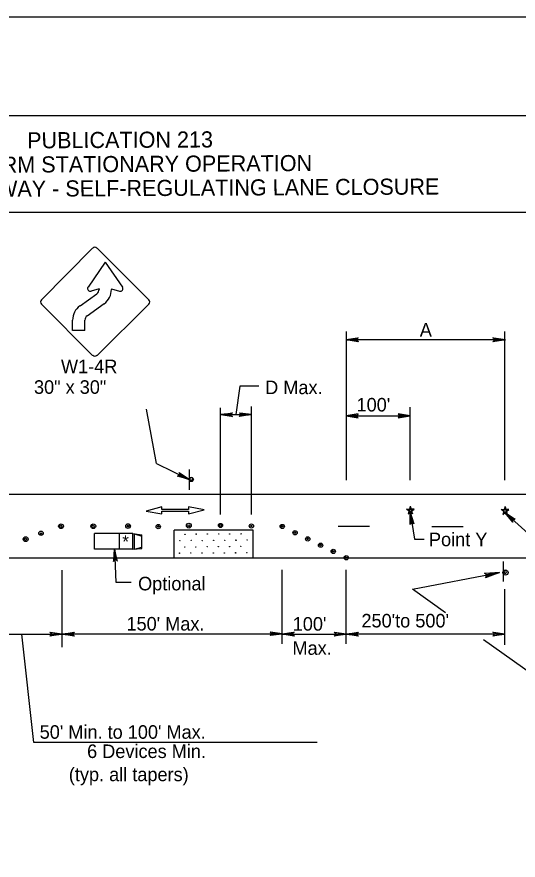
# Model space of a CAD drawing. Extents: x -14145 to -13521, y 30244 to 30661.
# Drawn here: x -13810.13 to -13802.36, y 30356.22 to 30369.31 of the extents above; entities that cross this region are included whole.
import ezdxf

# ---------------------------------------------------------------- set-up
doc = ezdxf.new("R2010")
doc.units = 0
for name, color, linetype in [('1', 7, 'Continuous'), ('10', 7, 'Continuous'), ('2', 7, 'Continuous'), ('3', 7, 'Continuous'), ('4', 7, 'Continuous'), ('61', 7, 'Continuous')]:
    doc.layers.add(name, color=color, linetype=linetype)

msp = doc.modelspace()

# ---------------------------------------------------------------- linework, layer by layer
at = {"layer": '1'}
for p, q in [((-13808.954, 30365.72), (-13809.748, 30364.917)), ((-13808.084, 30364.917), (-13808.886, 30365.72)), ((-13808.76, 30365.501), (-13809.026, 30365.114)), ((-13808.76, 30365.501), (-13808.49, 30365.114)), ((-13808.854, 30365.09), (-13808.978, 30365.051)), ((-13808.854, 30365.09), (-13808.854, 30365.078)), ((-13808.664, 30365.09), (-13808.538, 30365.051)), ((-13808.664, 30365.09), (-13808.664, 30365.079)), ((-13809.15, 30364.822), (-13808.888, 30365.012)), ((-13809.748, 30364.851), (-13808.954, 30364.056)), ((-13809.04, 30364.668), (-13808.776, 30364.858)), ((-13808.886, 30364.056), (-13808.084, 30364.851)), ((-13809.264, 30364.44), (-13809.264, 30364.601)), ((-13809.074, 30364.44), (-13809.074, 30364.603)), ((-13809.074, 30364.44), (-13809.264, 30364.44)), ((-13805.025, 30364.425), (-13805.025, 30362.12)), ((-13802.565, 30362.12), (-13802.565, 30364.426)), ((-13802.559, 30364.297), (-13805.025, 30364.297)), ((-13807.963, 30362.379), (-13808.121, 30363.219)), ((-13806.975, 30361.588), (-13806.975, 30363.244)), ((-13806.495, 30361.588), (-13806.495, 30363.262)), ((-13804.035, 30362.12), (-13804.035, 30363.25)), ((-13806.975, 30363.136), (-13806.495, 30363.136)), ((-13805.025, 30363.116), (-13804.035, 30363.116)), ((-13807.963, 30362.379), (-13807.457, 30362.128)), ((-13807.457, 30362.287), (-13807.457, 30361.969)), ((-13821.541, 30361.9), (-13795.261, 30361.9)), ((-13807.884, 30361.707), (-13808.125, 30361.641)), ((-13808.125, 30361.641), (-13807.881, 30361.595)), ((-13807.884, 30361.662), (-13807.884, 30361.707)), ((-13807.47, 30361.662), (-13807.884, 30361.662)), ((-13807.881, 30361.64), (-13807.467, 30361.64)), ((-13807.881, 30361.595), (-13807.881, 30361.64)), ((-13807.226, 30361.661), (-13807.47, 30361.707)), ((-13807.47, 30361.707), (-13807.47, 30361.662)), ((-13807.467, 30361.595), (-13807.226, 30361.661)), ((-13807.467, 30361.64), (-13807.467, 30361.595)), ((-13804.092, 30361.669), (-13804.046, 30361.669)), ((-13804.054, 30361.639), (-13804.092, 30361.669)), ((-13804.051, 30361.64), (-13804.085, 30361.666)), ((-13804.085, 30361.666), (-13804.044, 30361.666)), ((-13804.048, 30361.641), (-13804.078, 30361.664)), ((-13804.078, 30361.664), (-13804.042, 30361.664)), ((-13804.046, 30361.642), (-13804.071, 30361.661)), ((-13804.071, 30361.661), (-13804.04, 30361.661)), ((-13804.051, 30361.64), (-13804.062, 30361.602)), ((-13804.048, 30361.641), (-13804.058, 30361.608)), ((-13804.046, 30361.642), (-13804.053, 30361.615)), ((-13804.032, 30361.715), (-13804.046, 30361.669)), ((-13804.032, 30361.706), (-13804.044, 30361.666)), ((-13804.032, 30361.697), (-13804.042, 30361.664)), ((-13804.032, 30361.687), (-13804.04, 30361.661)), ((-13804.032, 30361.715), (-13804.019, 30361.669)), ((-13804.032, 30361.706), (-13804.021, 30361.666)), ((-13804.032, 30361.697), (-13804.023, 30361.664)), ((-13804.032, 30361.687), (-13804.025, 30361.661)), ((-13803.994, 30361.661), (-13804.025, 30361.661)), ((-13803.987, 30361.664), (-13804.023, 30361.664)), ((-13803.98, 30361.666), (-13804.021, 30361.666)), ((-13803.972, 30361.669), (-13804.019, 30361.669)), ((-13804.019, 30361.642), (-13803.994, 30361.661)), ((-13804.019, 30361.642), (-13804.012, 30361.615)), ((-13804.016, 30361.641), (-13803.987, 30361.664)), ((-13804.016, 30361.641), (-13804.007, 30361.608)), ((-13804.014, 30361.64), (-13803.98, 30361.666)), ((-13804.014, 30361.64), (-13804.003, 30361.602)), ((-13804.011, 30361.639), (-13803.972, 30361.669)), ((-13802.623, 30361.663), (-13802.577, 30361.663)), ((-13802.585, 30361.633), (-13802.623, 30361.663)), ((-13802.582, 30361.634), (-13802.616, 30361.66)), ((-13802.616, 30361.66), (-13802.575, 30361.66)), ((-13802.579, 30361.635), (-13802.609, 30361.658)), ((-13802.609, 30361.658), (-13802.573, 30361.658)), ((-13802.577, 30361.636), (-13802.602, 30361.655)), ((-13802.602, 30361.655), (-13802.571, 30361.655)), ((-13802.563, 30361.709), (-13802.577, 30361.663)), ((-13802.563, 30361.7), (-13802.575, 30361.66)), ((-13802.563, 30361.691), (-13802.573, 30361.658)), ((-13802.563, 30361.681), (-13802.571, 30361.655)), ((-13802.563, 30361.709), (-13802.55, 30361.663)), ((-13802.563, 30361.7), (-13802.552, 30361.66)), ((-13802.563, 30361.691), (-13802.554, 30361.658)), ((-13802.563, 30361.681), (-13802.556, 30361.655)), ((-13802.525, 30361.655), (-13802.556, 30361.655)), ((-13802.518, 30361.658), (-13802.554, 30361.658)), ((-13802.511, 30361.66), (-13802.552, 30361.66)), ((-13802.503, 30361.663), (-13802.55, 30361.663)), ((-13802.55, 30361.636), (-13802.525, 30361.655)), ((-13802.547, 30361.635), (-13802.518, 30361.658)), ((-13802.545, 30361.634), (-13802.511, 30361.66)), ((-13802.542, 30361.633), (-13802.503, 30361.663)), ((-13804.054, 30361.639), (-13804.067, 30361.595)), ((-13804.067, 30361.595), (-13804.032, 30361.622)), ((-13804.062, 30361.602), (-13804.032, 30361.625)), ((-13804.058, 30361.608), (-13804.032, 30361.628)), ((-13804.053, 30361.615), (-13804.032, 30361.631)), ((-13804.012, 30361.615), (-13804.032, 30361.631)), ((-13804.007, 30361.608), (-13804.032, 30361.628)), ((-13804.003, 30361.602), (-13804.032, 30361.625)), ((-13803.998, 30361.595), (-13804.032, 30361.622)), ((-13804.011, 30361.639), (-13803.998, 30361.595)), ((-13802.585, 30361.633), (-13802.598, 30361.589)), ((-13802.598, 30361.589), (-13802.563, 30361.616)), ((-13802.582, 30361.634), (-13802.593, 30361.596)), ((-13802.593, 30361.596), (-13802.563, 30361.619)), ((-13802.579, 30361.635), (-13802.589, 30361.602)), ((-13802.589, 30361.602), (-13802.563, 30361.622)), ((-13802.577, 30361.636), (-13802.584, 30361.609)), ((-13802.584, 30361.609), (-13802.563, 30361.625)), ((-13802.543, 30361.609), (-13802.563, 30361.625)), ((-13802.538, 30361.602), (-13802.563, 30361.622)), ((-13802.534, 30361.596), (-13802.563, 30361.619)), ((-13802.529, 30361.589), (-13802.563, 30361.616)), ((-13802.55, 30361.636), (-13802.543, 30361.609)), ((-13802.547, 30361.635), (-13802.538, 30361.602)), ((-13802.545, 30361.634), (-13802.534, 30361.596)), ((-13802.542, 30361.633), (-13802.529, 30361.589)), ((-13804.665, 30361.402), (-13805.151, 30361.402)), ((-13803.213, 30361.396), (-13803.699, 30361.396)), ((-13808.923, 30361.048), (-13808.923, 30361.294)), ((-13808.329, 30361.294), (-13808.923, 30361.294)), ((-13808.539, 30361.048), (-13808.539, 30361.294)), ((-13808.329, 30361.048), (-13808.329, 30361.294)), ((-13808.329, 30361.294), (-13808.191, 30361.27)), ((-13808.305, 30361.288), (-13808.191, 30361.252)), ((-13808.305, 30361.048), (-13808.305, 30361.288)), ((-13808.191, 30361.06), (-13808.191, 30361.27)), ((-13806.469, 30361.342), (-13807.693, 30361.342)), ((-13807.693, 30360.916), (-13807.693, 30361.342)), ((-13806.469, 30360.916), (-13806.469, 30361.342)), ((-13808.329, 30361.048), (-13808.923, 30361.048)), ((-13808.329, 30361.048), (-13808.191, 30361.06)), ((-13808.305, 30361.048), (-13808.191, 30361.078)), ((-13821.541, 30360.916), (-13795.261, 30360.916)), ((-13802.595, 30360.858), (-13802.595, 30360.546)), ((-13806.017, 30359.582), (-13806.017, 30360.728)), ((-13805.025, 30359.582), (-13805.025, 30360.728)), ((-13809.425, 30359.528), (-13809.425, 30360.722)), ((-13802.565, 30359.563), (-13802.565, 30360.427)), ((-13810.679, 30359.732), (-13809.431, 30359.732)), ((-13806.017, 30359.732), (-13809.425, 30359.732)), ((-13806.017, 30359.732), (-13805.025, 30359.732)), ((-13802.565, 30359.732), (-13805.025, 30359.732))]:
    msp.add_line(p, q, dxfattribs=at)
for points in [[(-13804.845, 30364.279), (-13804.851, 30364.291), (-13805.025, 30364.297), (-13804.845, 30364.279), (-13804.839, 30364.267), (-13805.025, 30364.297), (-13804.857, 30364.309), (-13804.851, 30364.321), (-13805.025, 30364.297), (-13804.839, 30364.327), (-13804.851, 30364.321)], [(-13802.739, 30364.321), (-13802.733, 30364.309), (-13802.559, 30364.297), (-13802.739, 30364.321), (-13802.751, 30364.327), (-13802.559, 30364.297), (-13802.733, 30364.291), (-13802.739, 30364.279), (-13802.559, 30364.297), (-13802.751, 30364.267), (-13802.739, 30364.279)], [(-13806.377, 30363.58), (-13806.671, 30363.58), (-13806.735, 30363.136)], [(-13806.801, 30363.112), (-13806.807, 30363.124), (-13806.975, 30363.136), (-13806.801, 30363.112), (-13806.789, 30363.106), (-13806.975, 30363.136), (-13806.807, 30363.142), (-13806.801, 30363.154), (-13806.975, 30363.136), (-13806.789, 30363.166), (-13806.801, 30363.154)], [(-13806.675, 30363.16), (-13806.669, 30363.148), (-13806.495, 30363.136), (-13806.675, 30363.16), (-13806.681, 30363.166), (-13806.495, 30363.136), (-13806.669, 30363.13), (-13806.675, 30363.118), (-13806.495, 30363.136), (-13806.681, 30363.106), (-13806.675, 30363.118)], [(-13804.845, 30363.134), (-13804.857, 30363.122), (-13805.025, 30363.116), (-13804.845, 30363.134), (-13804.839, 30363.146), (-13805.025, 30363.116), (-13804.857, 30363.104), (-13804.851, 30363.092), (-13805.025, 30363.116), (-13804.839, 30363.086), (-13804.851, 30363.092)], [(-13804.215, 30363.092), (-13804.203, 30363.11), (-13804.035, 30363.116), (-13804.215, 30363.092), (-13804.221, 30363.086), (-13804.035, 30363.116), (-13804.203, 30363.122), (-13804.209, 30363.14), (-13804.035, 30363.116), (-13804.221, 30363.146), (-13804.209, 30363.14)], [(-13807.609, 30362.227), (-13807.609, 30362.21), (-13807.457, 30362.128), (-13807.609, 30362.227), (-13807.611, 30362.236), (-13807.457, 30362.128), (-13807.615, 30362.193), (-13807.627, 30362.188), (-13807.457, 30362.128), (-13807.641, 30362.182), (-13807.627, 30362.188)], [(-13804.029, 30361.44), (-13804.013, 30361.454), (-13804.033, 30361.621), (-13804.029, 30361.44), (-13804.033, 30361.432), (-13804.033, 30361.621), (-13804.001, 30361.456), (-13803.983, 30361.453), (-13804.033, 30361.621), (-13803.975, 30361.442), (-13803.983, 30361.453)], [(-13802.446, 30361.477), (-13802.442, 30361.498), (-13802.563, 30361.615), (-13802.446, 30361.477), (-13802.445, 30361.468), (-13802.563, 30361.615), (-13802.434, 30361.507), (-13802.418, 30361.516), (-13802.563, 30361.615), (-13802.406, 30361.512), (-13802.418, 30361.516)], [(-13808.583, 30360.876), (-13808.595, 30360.882), (-13808.613, 30361.048), (-13808.583, 30360.876), (-13808.571, 30360.865), (-13808.613, 30361.048), (-13808.613, 30360.88), (-13808.625, 30360.874), (-13808.613, 30361.048), (-13808.631, 30360.86), (-13808.625, 30360.874)], [(-13808.356, 30360.53), (-13808.592, 30360.53), (-13808.612, 30361.048)], [(-13805.477, 30358.052), (-13809.867, 30358.052), (-13810.054, 30359.732)], [(-13809.611, 30359.756), (-13809.599, 30359.738), (-13809.431, 30359.732), (-13809.611, 30359.756), (-13809.617, 30359.762), (-13809.431, 30359.732), (-13809.599, 30359.726), (-13809.605, 30359.708), (-13809.431, 30359.732), (-13809.617, 30359.702), (-13809.605, 30359.708)], [(-13809.245, 30359.708), (-13809.251, 30359.72), (-13809.425, 30359.732), (-13809.245, 30359.708), (-13809.239, 30359.702), (-13809.425, 30359.732), (-13809.251, 30359.738), (-13809.245, 30359.75), (-13809.425, 30359.732), (-13809.239, 30359.762), (-13809.245, 30359.75)], [(-13806.197, 30359.762), (-13806.191, 30359.744), (-13806.017, 30359.738), (-13806.197, 30359.762), (-13806.203, 30359.768), (-13806.017, 30359.738), (-13806.191, 30359.732), (-13806.197, 30359.714), (-13806.017, 30359.738), (-13806.203, 30359.708), (-13806.197, 30359.714)], [(-13805.837, 30359.714), (-13805.849, 30359.726), (-13806.017, 30359.732), (-13805.837, 30359.714), (-13805.831, 30359.702), (-13806.017, 30359.732), (-13805.849, 30359.744), (-13805.843, 30359.756), (-13806.017, 30359.732), (-13805.831, 30359.762), (-13805.843, 30359.756)], [(-13805.205, 30359.756), (-13805.193, 30359.738), (-13805.025, 30359.732), (-13805.205, 30359.756), (-13805.211, 30359.762), (-13805.025, 30359.732), (-13805.193, 30359.726), (-13805.199, 30359.708), (-13805.025, 30359.732), (-13805.211, 30359.702), (-13805.199, 30359.708)], [(-13804.845, 30359.708), (-13804.851, 30359.72), (-13805.025, 30359.732), (-13804.845, 30359.708), (-13804.839, 30359.702), (-13805.025, 30359.732), (-13804.851, 30359.738), (-13804.845, 30359.75), (-13805.025, 30359.732), (-13804.839, 30359.762), (-13804.845, 30359.75)], [(-13802.745, 30359.756), (-13802.739, 30359.738), (-13802.565, 30359.732), (-13802.745, 30359.756), (-13802.751, 30359.762), (-13802.565, 30359.732), (-13802.739, 30359.726), (-13802.745, 30359.708), (-13802.565, 30359.732), (-13802.751, 30359.702), (-13802.745, 30359.708)]]:
    msp.add_lwpolyline(points, dxfattribs=at)
for centre, radius in [((-13807.424, 30362.13), 0.0325), ((-13809.444, 30361.405), 0.037), ((-13809.444, 30361.405), 0.037), ((-13809.447, 30361.403), 0.0172), ((-13809.447, 30361.403), 0.0172), ((-13808.944, 30361.405), 0.037), ((-13808.947, 30361.403), 0.0172), ((-13808.405, 30361.407), 0.0353), ((-13808.402, 30361.408), 0.014), ((-13807.937, 30361.399), 0.0331), ((-13807.938, 30361.4), 0.012), ((-13807.464, 30361.414), 0.037), ((-13807.464, 30361.413), 0.0149), ((-13806.973, 30361.417), 0.0321), ((-13806.972, 30361.415), 0.0143), ((-13806.494, 30361.409), 0.0327), ((-13806.496, 30361.409), 0.00928), ((-13806.016, 30361.401), 0.0331), ((-13806.017, 30361.402), 0.012), ((-13809.755, 30361.296), 0.0346), ((-13809.754, 30361.291), 0.0101), ((-13807.522, 30361.281), 0.00272), ((-13807.35, 30361.282), 0.00272), ((-13807.176, 30361.283), 0.00272), ((-13807.001, 30361.282), 0.00272), ((-13806.83, 30361.284), 0.00272), ((-13806.655, 30361.287), 0.00272), ((-13805.818, 30361.304), 0.0331), ((-13805.82, 30361.305), 0.012), ((-13809.992, 30361.205), 0.038), ((-13809.993, 30361.202), 0.0155), ((-13807.602, 30361.183), 0.00272), ((-13807.427, 30361.185), 0.00272), ((-13807.256, 30361.183), 0.00272), ((-13807.08, 30361.185), 0.00272), ((-13806.907, 30361.184), 0.00272), ((-13806.735, 30361.189), 0.00272), ((-13806.733, 30361.186), 0.00272), ((-13806.56, 30361.191), 0.00272), ((-13805.621, 30361.208), 0.0331), ((-13805.622, 30361.209), 0.012), ((-13805.423, 30361.111), 0.0331), ((-13805.424, 30361.112), 0.012), ((-13807.608, 30360.987), 0.00272), ((-13807.528, 30361.085), 0.00272), ((-13807.433, 30360.989), 0.00272), ((-13807.356, 30361.085), 0.00272), ((-13807.26, 30360.988), 0.00272), ((-13807.179, 30361.086), 0.00272), ((-13807.086, 30360.99), 0.00272), ((-13807.007, 30361.086), 0.00272), ((-13806.912, 30360.991), 0.00272), ((-13806.831, 30361.087), 0.00272), ((-13806.74, 30360.994), 0.00272), ((-13806.738, 30360.991), 0.00272), ((-13806.66, 30361.091), 0.00272), ((-13806.565, 30360.995), 0.00272), ((-13805.226, 30361.014), 0.0331), ((-13805.227, 30361.015), 0.012), ((-13805.025, 30360.916), 0.0331), ((-13805.026, 30360.917), 0.012), ((-13802.556, 30360.686), 0.0408)]:
    msp.add_circle(centre, radius, dxfattribs=at)
for centre, radius, start, end in [((-13808.92, 30365.687), 0.0465, 45, 135), ((-13808.991, 30365.092), 0.0422, 148.3587, 286.1741), ((-13808.936, 30365.079), 0.082, 305.7926, 359.6684), ((-13808.935, 30365.078), 0.272, 305.7541, 0.1328), ((-13808.527, 30365.092), 0.0422, 253.8088, 31.6584), ((-13809.715, 30364.885), 0.0465, 135, 225), ((-13808.117, 30364.884), 0.0465, 315, 45), ((-13808.992, 30364.603), 0.272, 125.7541, 180.1328), ((-13808.992, 30364.603), 0.081, 125.4525, 180.0086), ((-13808.92, 30364.089), 0.0465, 225, 315), ((-13807.424, 30362.141), 0.0214, 189.521, 184.2501), ((-13802.561, 30360.694), 0.0214, 189.521, 184.2501)]:
    msp.add_arc(centre, radius, start, end, dxfattribs=at)
at = {"layer": '10'}
for p, q in [((-13823.874, 30367.777), (-13792.422, 30367.777)), ((-13823.874, 30366.277), (-13792.422, 30366.277))]:
    msp.add_line(p, q, dxfattribs=at)
at = {"layer": '2'}
for p, q in [((-13804.033, 30361.621), (-13803.967, 30361.202)), ((-13802.563, 30361.615), (-13802.106, 30361.202)), ((-13803.967, 30361.202), (-13803.817, 30361.202))]:
    msp.add_line(p, q, dxfattribs=at)
at = {"layer": '3'}
for points in [[(-13803.487, 30360.063), (-13803.998, 30360.427), (-13802.65, 30360.685)], [(-13802.87, 30360.671), (-13802.859, 30360.657), (-13802.65, 30360.685), (-13802.87, 30360.671), (-13802.882, 30360.678), (-13802.65, 30360.685), (-13802.854, 30360.635), (-13802.859, 30360.618), (-13802.65, 30360.685), (-13802.869, 30360.606), (-13802.859, 30360.618)], [(-13801.529, 30358.669), (-13802.898, 30359.644)]]:
    msp.add_lwpolyline(points, dxfattribs=at)
at = {"layer": '61'}
msp.add_lwpolyline([(-13824.174, 30369.307), (-13791.174, 30369.307), (-13791.174, 30343.807), (-13824.174, 30343.807)], close=True, dxfattribs=at)

# ---------------------------------------------------------------- texts
at = {"layer": '1'}
msp.add_text('*', height=0.198, rotation=0.7233, dxfattribs=at).set_placement((-13808.493, 30361.067))
at = {"layer": '2'}
for s, p in [('A', (-13803.885, 30364.347)), ('W1-4R', (-13809.445, 30363.779)), ('30" x 30"', (-13809.863, 30363.459)), ('D Max.', (-13806.281, 30363.454)), ("100'", (-13804.865, 30363.185)), ('Optional', (-13808.25, 30360.41)), ("150' Max.", (-13808.43, 30359.787)), ("100'", (-13805.854, 30359.785)), ("250'to 500'", (-13804.789, 30359.835)), ('Max.', (-13805.858, 30359.41)), ("50' Min. to 100' Max.", (-13809.775, 30358.108)), ('6 Devices Min.', (-13809.04, 30357.809)), ('(typ. all tapers)', (-13809.323, 30357.45))]:
    msp.add_text(s, height=0.21, dxfattribs=at).set_placement(p)
at = {"layer": '3'}
msp.add_text('Point Y', height=0.21, dxfattribs=at).set_placement((-13803.743, 30361.095))
at = {"layer": '4'}
for s, p in [('PUBLICATION 213', (-13809.969, 30367.266)), ('LONG-TERM STATIONARY OPERATION', (-13811.849, 30366.881)), ('TWO-LANE, TWO-WAY ROADWAY - SELF-REGULATING LANE CLOSURE', (-13815.097, 30366.489))]:
    msp.add_text(s, height=0.25, rotation=0.31, dxfattribs=at).set_placement(p)

doc.saveas('drawing.dxf')
